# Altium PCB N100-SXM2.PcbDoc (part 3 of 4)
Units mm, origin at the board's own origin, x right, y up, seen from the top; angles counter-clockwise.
Board outline 120 x 145 mm, 4 copper layers (Top Layer, GND, PWR, Bottom Layer), stack 0.603 mm thick; 267 components, 207 nets, 1440 pads, 915 vias.
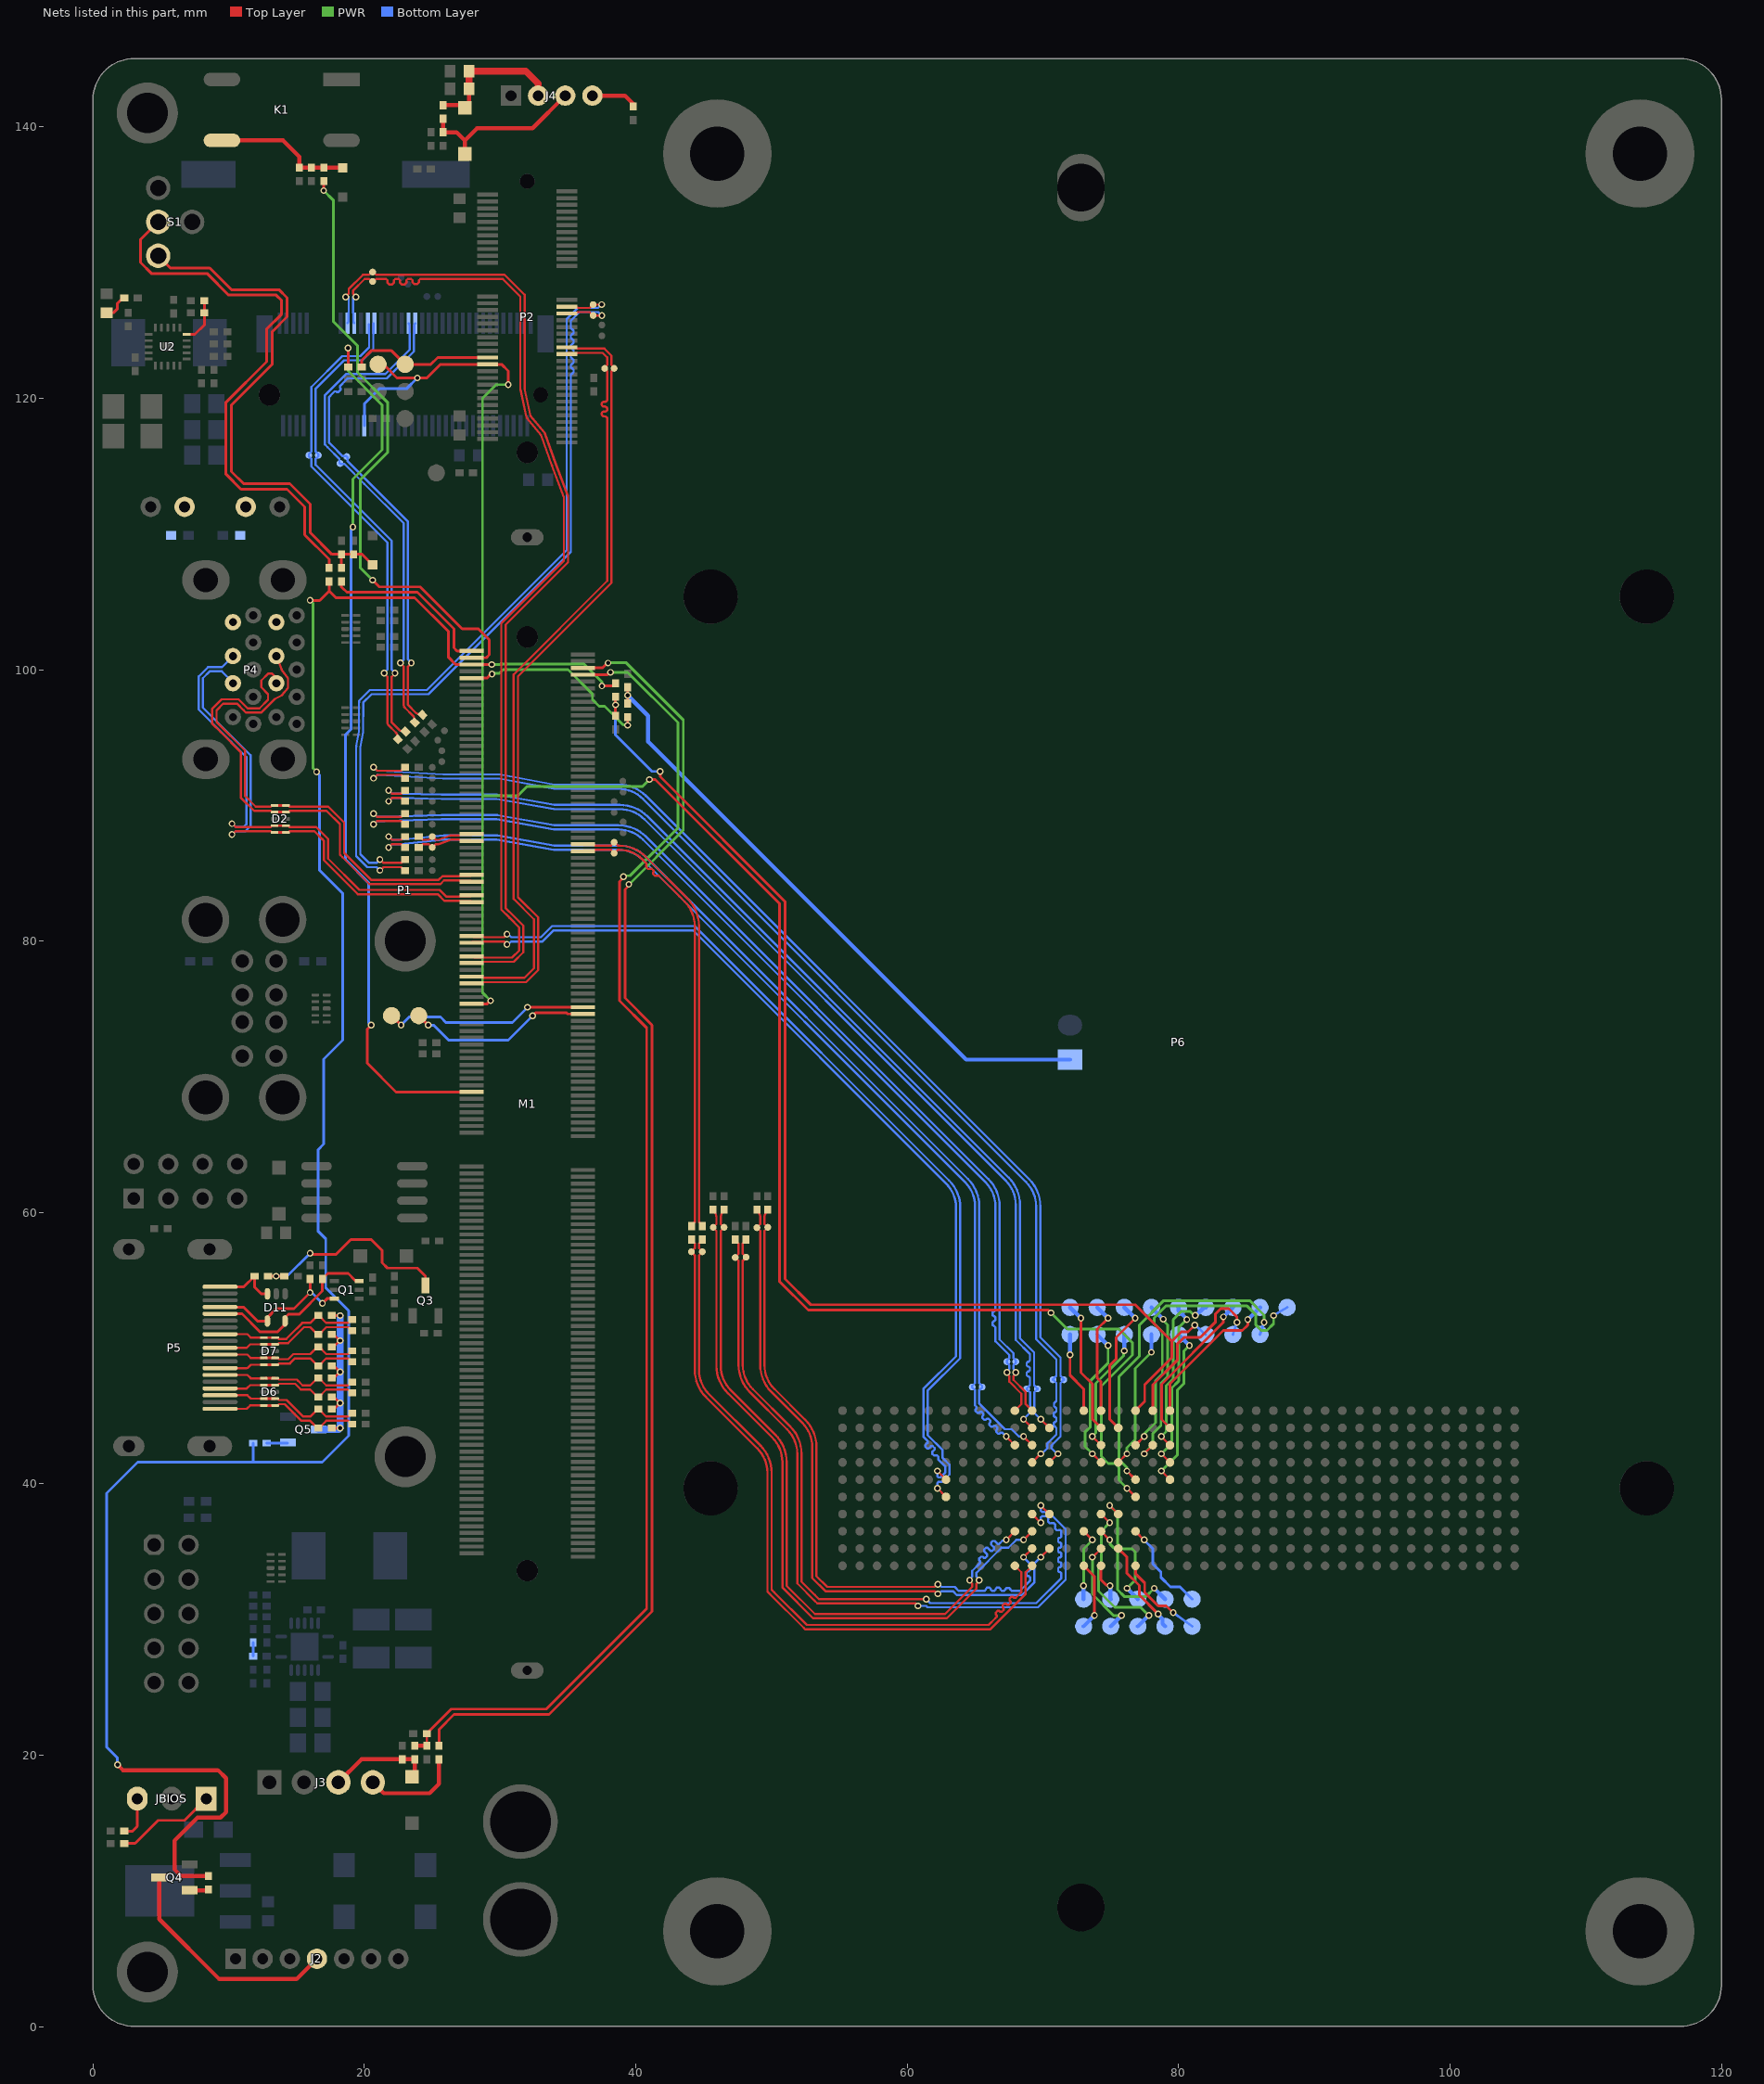
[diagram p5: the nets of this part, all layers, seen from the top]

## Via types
v1: diameter 0.5, hole 0.3, Top Layer to Bottom Layer, tented both sides, 908 vias
v2: diameter 0.6, hole 0.3, Top Layer to Bottom Layer, tented both sides, 6 vias
v3: diameter 1.5, hole 1.5, Top Layer to Bottom Layer, tented both sides, 1 vias

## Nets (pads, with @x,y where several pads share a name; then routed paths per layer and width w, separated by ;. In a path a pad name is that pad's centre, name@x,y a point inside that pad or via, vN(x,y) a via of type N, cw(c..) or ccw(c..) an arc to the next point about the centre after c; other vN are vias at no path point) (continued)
HSIO11_RX_n: C49.2 M1.60 TP32.1 | length 33.8
  Top Layer w0.161: M1.60@36.1,86.625 cw(c36.268,86.457) 36.268,86.694 36.946,86.694 ccw(c36.946,86.737) 36.976,86.707 cw(c37.006,86.677) 37.006,86.719 38.155,86.719 TP32.1@38.4,86.475 38.419,86.475 38.664,86.719 38.8,86.719 cw(c38.8,84.352) 40.474,86.026 40.786,85.714 40.786,85.581 40.772,85.566 40.772,85.438 40.899,85.311 41.027,85.311 41.044,85.328 41.172,85.328 41.299,85.201 41.299,85.073 41.282,85.056 41.282,84.928 41.41,84.8 41.537,84.8 41.552,84.815 41.685,84.815 43.198,83.302 43.601,82.899 cw(c41.804,81.103) 44.344,81.103 44.344,60.054 44.344,59.291 44.1,59.046 C49.2@44.1,59
HSIO11_RX_p: C48.2 M1.58 TP31.1 | length 33.9
  Top Layer w0.161: M1.58@36.1,87.125 ccw(c36.268,87.293) 36.268,87.055 36.946,87.055 cw(c36.946,87.013) 36.976,87.043 ccw(c37.006,87.073) 37.006,87.03 38.156,87.03 TP31.1@38.4,87.275 38.419,87.275 38.664,87.03 38.804,87.03 cw(c38.804,84.362) 40.691,86.249 43.823,83.117 cw(c41.813,81.107) 44.655,81.107 44.655,60.183 44.655,59.29 44.9,59.046 C48.2@44.9,59
HSIO11_TX_n: C41.2 M1.57 TP24.1 | length 4.3
  Top Layer w0.161: C41.2@24,86.9 24.046,86.9 24.291,87.145 24.736,87.145 24.981,86.9 TP24.1@25,86.9 25.019,86.9 25.264,87.144 25.451,87.144 ; 25.452,87.145 ccw(c25.451,87.455) 25.557,87.163 ; 25.557,87.163 26.4,87.469 27.011,87.469 27.036,87.444 27.831,87.444 M1.57@27.9,87.375
HSIO11_TX_p: C40.2 M1.55 TP23.1 | length 4.3
  Top Layer w0.161: C40.2@24,87.7 24.046,87.7 24.291,87.456 24.736,87.456 24.981,87.7 TP23.1@25,87.7 25.019,87.7 25.264,87.455 25.451,87.455 26.293,87.761 cw(c26.4,87.469) 26.399,87.78 ; 26.4,87.78 27.011,87.78 27.036,87.805 27.831,87.805 M1.55@27.9,87.875
JSEL: P6.C19 TP53.1 | length 12.9
  Top Layer w0.161: v1(77.46,42.215) P6.C19@78.095,42.85
  PWR w0.2: v1(77.46,42.215) 77.46,42.242 78.1,42.882 78.1,43.7 78.7,44.3 78.7,47.4 79.2,47.9 79.2,51.719 78.872,52.047 v1(78.872,52.128)
  Bottom Layer w0.3: TP53.1@78,53 v1(78.872,52.128)
JTCK: P6.C20 TP50.1 | length 12.9
  Top Layer w0.161: v1(78.73,43.485) P6.C20@79.365,42.85
  PWR w0.2: v1(78.73,43.485) 79.1,43.855 79.1,47.231 79.6,47.731 79.6,52.1 80.2,52.7 80.858,52.7 81.145,52.413 v1(81.226,52.413)
  Bottom Layer w0.3: v1(81.226,52.413) 81.28,52.413 81.868,53 TP50.1@82,53
JTDI: P6.E20 TP52.1 | length 12.1
  Top Layer w0.161: v1(78.73,40.945) P6.E20@79.365,40.31
  PWR w0.2: v1(78.73,40.945) 79.9,42.115 79.9,46.9 80.4,47.4 80.4,49.8 v1(80.8,50.2)
  Bottom Layer w0.3: TP52.1@80,51 v1(80.8,50.2)
JTDO: P6.D20 TP51.1 | length 12.7
  Top Layer w0.161: v1(78.73,42.215) P6.D20@79.365,41.58
  PWR w0.2: v1(78.73,42.215) 79.5,42.985 79.5,47.066 80,47.566 80,51.5 v1(80.6,52.1)
  Bottom Layer w0.3: TP51.1@80,53 80,52.754 80.6,52.154 v1(80.6,52.1)
JTMS: P6.B20 TP49.1 | length 11.3
  Top Layer w0.2: P6.B20@79.365,44.12 78.745,44.74 78.745,47.345 83.3,51.9 v1(83.3,52.3)
  Bottom Layer w0.3: v1(83.3,52.3) TP49.1@84,53
JTRST: P6.A20 TP48.1 | length 11.2
  Top Layer w0.2: P6.A20@79.365,45.39 79.365,47.365 83.3,51.3 84.7,51.3 85.1,51.7 v1(85.1,52.1)
  Bottom Layer w0.3: v1(85.1,52.1) TP48.1@86,53
M.2_1_RX0_n: C5.1 P1.47 TP73.1 | length 35.9
  Top Layer w0.161: v1(22.255,99.736) 22.255,99.717 22.011,99.472 22.011,96.109 22.529,95.591 ccw(c22.824,95.886) 22.824,95.469 22.951,95.469 cw(c22.951,95.358) C5.1@23.029,95.436
  Bottom Layer w0.161: P1.47@20.681,125.525 20.681,124.761 20.656,124.736 20.656,123.616 19.831,122.791 18.491,122.791 16.405,120.705 16.405,116.064 16.6,115.869 TP73.1@16.6,115.8 16.6,115.731 16.405,115.536 16.405,115.095 22.011,109.489 22.011,100 22.255,99.755 v1(22.255,99.736)
M.2_1_RX0_p: C6.1 P1.49 TP77.1 | length 36.1
  Top Layer w0.161: v1(21.455,99.736) 21.455,99.717 21.7,99.472 21.7,96.108 ccw(c22.009,96.108) 21.79,95.89 22.309,95.371 cw(c22.014,95.076) 22.431,95.076 22.431,94.949 ccw(c22.542,94.949) C6.1@22.464,94.871
  Bottom Layer w0.161: P1.49@20.319,125.456 20.319,124.761 20.345,124.736 20.345,123.744 19.702,123.102 18.362,123.102 16.094,120.834 16.094,116.064 15.9,115.869 TP77.1@15.9,115.8 15.9,115.731 16.094,115.536 16.094,114.966 21.7,109.36 21.7,100 21.455,99.755 v1(21.455,99.736)
M.2_1_RX1_n: C3.1 P1.35 TP67.1 | length 36.8
  Top Layer w0.161: v1(23.455,100.49) 23.455,100.47 23.211,100.226 23.211,97.4 23.783,96.828 ccw(c24.078,97.123) 24.078,96.705 24.205,96.705 cw(c24.205,96.594) C3.1@24.284,96.673
  Bottom Layer w0.161: v1(23.455,100.49) 23.455,100.509 23.211,100.753 23.211,110.909 18.746,115.373 18.746,115.654 TP67.1@18.7,115.7 18.654,115.746 18.373,115.746 17.601,116.519 17.4,116.72 17.4,120.1 17.491,120.191 17.803,120.503 17.936,120.503 17.979,120.461 18.081,120.461 18.234,120.614 18.234,120.716 18.192,120.758 18.192,120.892 18.625,121.325 18.764,121.464 21.654,121.464 23.656,123.466 23.656,124.719 cw(c23.698,124.719) 23.668,124.749 ccw(c23.638,124.779) 23.681,124.779 23.681,125.357 cw(c23.918,125.357) P1.35@23.75,125.525
M.2_1_RX1_p: C4.1 P1.37 TP71.1 | length 36.8
  Top Layer w0.161: v1(22.655,100.49) 22.655,100.47 22.9,100.226 22.9,97.399 ccw(c23.209,97.399) 22.99,97.18 23.563,96.608 cw(c23.268,96.313) 23.685,96.313 23.685,96.186 ccw(c23.796,96.186) C4.1@23.718,96.107
  Bottom Layer w0.161: v1(22.655,100.49) 22.655,100.509 22.9,100.753 22.9,110.78 19.99,113.69 18.527,115.154 18.246,115.154 TP71.1@18.2,115.2 18.153,115.247 18.153,115.527 17.29,116.39 17.089,116.591 17.089,120.229 18.635,121.775 21.525,121.775 23.344,123.595 23.344,124.719 ccw(c23.302,124.719) 23.332,124.749 cw(c23.362,124.779) 23.32,124.779 23.32,125.357 ccw(c23.082,125.357) P1.37@23.25,125.525
M.2_E_n: C63.1 P2.35 TP81.1 | length 58.4
  Top Layer w0.161: v1(21.136,85.2) 21.155,85.2 21.4,85.445 22.71,85.445 22.954,85.2 C63.1@23,85.2 ; P2.35@34.93,126.75 34.999,126.68 35.694,126.68 35.719,126.655 36.592,126.655 36.836,126.9 TP81.1@36.855,126.9 v1(37.481,126.9)
  Bottom Layer w0.161: v1(21.136,85.2) 20.892,85.444 20.216,85.444 19.389,86.271 19.389,94.3 cw(c19.7,94.3) 19.389,94.301 cw(c19.7,94.3) 19.394,94.357 19.591,95.442 ccw(c19.433,95.469) 19.594,95.468 19.594,97.571 19.6,97.578 19.6,97.7 20.4,98.5 24.6,98.5 34.9,108.8 34.9,125.84 35.716,126.655 37.217,126.655 37.461,126.9 v1(37.481,126.9)
M.2_E_p: C64.1 P2.37 TP82.1 | length 58.3
  Top Layer w0.161: v1(21.136,86) 21.155,86 21.4,85.756 22.71,85.756 22.954,86 C64.1@23,86 ; P2.37@34.93,126.25 34.999,126.319 35.694,126.319 35.719,126.344 36.592,126.344 36.836,126.1 TP82.1@36.855,126.1 v1(37.5,126.1)
  Bottom Layer w0.161: v1(21.136,86) 20.892,85.755 20.345,85.755 19.7,86.4 19.7,94.3 19.897,95.386 ccw(c19.591,95.442) 19.899,95.393 ccw(c19.433,95.469) 19.905,95.467 19.911,97.571 20.529,98.189 24.729,98.189 35.211,108.671 35.211,121.292 35.211,121.734 35.305,121.828 35.324,121.828 35.415,121.919 35.415,122.099 35.324,122.189 35.301,122.189 35.211,122.28 35.211,122.46 35.301,122.55 35.324,122.55 35.415,122.641 35.415,122.821 35.324,122.911 35.301,122.911 35.211,123.002 35.211,123.182 35.301,123.272 35.324,123.272 35.415,123.363 35.415,123.543 35.324,123.633 35.301,123.633 35.211,123.724 35.211,123.904 35.301,123.994 35.324,123.994 35.415,124.085 35.415,124.265 35.324,124.355 35.301,124.355 35.211,124.446 35.211,124.626 35.301,124.716 35.324,124.716 35.415,124.807 35.415,124.987 35.324,125.077 35.305,125.077 35.211,125.172 35.211,125.5 35.211,125.711 35.844,126.344 37.236,126.344 37.481,126.1 v1(37.5,126.1)
NetC56_2: C56.2 R37.2 | length 1
  Bottom Layer w0.2: C56.2@11.8,27.3 R37.2@11.8,28.3
NetC67_2: C67.2 D16.1 K1.4 R49.2 R50.2 | length 10
  Top Layer w0.3: K1.4@9.5,139 14,139 15.2,137.8 C67.2@15.2,137 ; C67.2@15.4,137 R50.2@16.1,137 R49.2@17,137 D16.1@18.375,137
NetC68_2: C68.2 D17.1 R46.2 R47.2 S1.2 | length 40.8
  Top Layer w0.2: S1.2@4.8,130.5 5.7,129.6 8.6,129.6 10.2,128 13.7,128 14.3,127.4 14.3,126 13.2,124.9 13.2,122.5 10.2,119.5 10.2,114.6 11.1,113.7 14.5,113.7 16,112.2 16,110.1 17.6,108.5 R46.2@18.3,108.5 ; R47.2@18.3,107.5 R46.2@18.3,108.5 ; D17.1@20.6,107.725 19.825,108.5 C68.2@19.2,108.5 R46.2@18.3,108.5
NetD8_2: D8.2 J3.3 R7.2 R8.1 | length 7.5
  Top Layer w0.3: J3.3@18.08,18 19.78,19.7 R7.2@22.8,19.7 R8.1@23.7,19.7 D8.2@23.7,18.5
NetD9_1: D9.1 J4.2 R18.2 R19.2 R20.1 | length 10.7
  Top Layer w0.3: R20.1@25.8,141.6 D9.1@27.2,141.6 ; D9.1@27.3,141.5 D9.1@27.4,141.4 ; D9.1@27.45,141.45 27.7,141.7 R18.2@27.7,142.8
  Top Layer w0.5: R18.2@27.7,142.8 R19.2@27.7,144.1 31.9,144.1 32.8,143.2 J4.2@32.8,142.3
NetD9_2: D9.2 J4.3 R20.2 R21.1 | length 12.6
  Top Layer w0.3: R20.2@25.8,140.6 R21.1@25.8,139.6 26.8,139.6 27.4,139 ; D9.2@27.4,138 27.4,139 ; J4.3@34.8,142.3 32.4,139.9 28.3,139.9 27.4,139
NetD14_2: D14.2 R44.2 | length 2
  Top Layer w0.2: D14.2@1,126.3 1.5,126.3 1.8,126.6 1.8,127 2.2,127.4 R44.2@2.3,127.4
NetJ3_4: J3.4 R9.1 | length 7.3
  Top Layer w0.3: J3.4@20.62,18 21.22,17.4 21.42,17.2 24.8,17.2 25.5,17.9 R9.1@25.5,19.7
NetJ4_4: J4.4 R22.1 | length 3.2
  Top Layer w0.3: J4.4@36.8,142.3 39.2,142.3 R22.1@39.8,141.7
NetJBIOS_1: JBIOS.1 R2.1 | length 7.4
  Top Layer w0.2: R2.1@2.3,13.5 3.1,13.5 4.8,15.2 6.74,15.2 JBIOS.1@8.34,16.8
NetJBIOS_3: JBIOS.3 R3.1 | length 3.1
  Top Layer w0.2: R3.1@2.3,14.4 2.9,14.4 3.26,14.76 JBIOS.3@3.26,16.8
NetQ3_3: Q3.3 R29.2 R31.2 | length 15.7
  Top Layer w0.2: R29.2@12.9,55.3 v1(13.5,55.3) R31.2@14.1,55.3 ; v1(16,57) 16.1,56.9 17.9,56.9 19,58 20.5,58 21.3,57.2 21.3,56.3 21.7,55.9 23.9,55.9 24.5,55.3 Q3.3@24.5,54.625
  Bottom Layer w0.2: v1(13.5,55.3) 14.3,55.3 v1(16,57)
NetQ4_1: Q4.1 R30.1 | length 1.3
  Top Layer w0.3: Q4.1@7.125,10.05 R30.1@8.45,10.05
NetQ5_1: Q5.1 R23.1 | length 1.5
  Bottom Layer w0.2: R23.1@12.8,43 Q5.1@14.325,43
NetQ5_3: Q5.3 R14.1 R15.2 R51.1 R52.2 R53.1 R54.2 R55.1 R56.2 | length 15.4
  Top Layer w0.2: R15.2@17.6,44.1 v1(18.2,44.1) ; R52.2@17.6,45.5 17.75,45.5 v1(18.2,45.95) R54.2@17.75,46.4 ; R56.2@17.6,47.8 17.75,47.8 v1(18.2,48.25) R14.1@17.75,48.7 ; R51.1@17.6,50.1 17.75,50.1 v1(18.2,50.55) R53.1@17.75,51 ; R55.1@17.6,52.4 v1(18.2,52.4)
  Bottom Layer w0.5: Q5.3@16.625,44 18.1,44 v1(18.2,44.1) v1(18.2,45.95) v1(18.2,48.25) v1(18.2,52.4)
NetR12_1: R12.1 R40.1 U2.15 | length 3.4
  Top Layer w0.2: U2.15@6.9,124.7 7.5,124.7 8.2,125.4 R40.1@8.2,127.2
NetR48_2: R48.2 S1.4 | length 41.6
  Top Layer w0.2: S1.4@4.8,133 3.5,131.7 3.5,130 4.3,129.2 8.4,129.2 10,127.6 13.5,127.6 13.9,127.2 13.9,126.2 12.8,125.1 12.8,122.7 9.8,119.7 9.8,114.4 10.9,113.3 14.3,113.3 15.6,112 15.6,109.934 17.4,108.134 R48.2@17.4,107.5
NTC: NTC.1 R16.2 R17.1 | length 46
  Top Layer w0.2: R17.1@39.4,97.5 v1(39.4,98.1) R16.2@39.4,98.7
  Bottom Layer w0.3: v1(39.4,98.1) 40.9,96.6 40.9,94.7 64.34,71.26 NTC.1@72,71.26
PERST#: M1.105 P1.50 P2.52 P6.F18 TP61.1 | length 161.9
  Top Layer w0.161: v1(76.19,39.675) P6.F18@76.825,39.04
  Top Layer w0.2: TP61.1@21,122.5 21.205,122.295 21.605,122.295 22.4,121.5 24.6,121.5 25.6,122.5 P2.52@29.07,122.5 30.1,122.5 30.6,122 v1(30.6,121) ; M1.105@27.9,75.375 29.044,75.375 29.269,75.6 v1(29.3,75.6) ; v1(41,91.9) 41.434,91.9 50.6,82.734 50.6,54.9 52.7,52.8 70.4,52.8 v1(70.6,52.6)
  PWR w0.2: v1(29.3,75.6) 28.7,76.2 28.7,90.7 ; v1(30.6,121) 29.7,121 28.7,120 28.7,90.7 ; v1(41,91.9) 40.5,91.4 32,91.4 31.3,90.7 28.7,90.7 ; v1(70.6,52.6) 71.8,51.4 75.6,51.4 76.6,50.4 76.6,49.5 74.3,47.2 74.3,42.029 74.829,41.5 75.3,41.5 75.6,41.2 75.6,40.265 v1(76.19,39.675)
  Bottom Layer w0.2: P1.50@20,117.975 20,119.6 21.1,120.7 23.1,120.7 v1(23.9,121.5)
PSON#: J2.4 Q4.3 | length 17.2
  Top Layer w0.3: Q4.3@4.875,11 4.875,7.925 9.3,3.5 15,3.5 J2.4@16.5,5
PWRBTN: M1.1 R47.1 | length 12.9
  Top Layer w0.2: R47.1@18.3,106.5 18.3,106.1 18.5,105.9 ; 18.4,106 18.7,105.7 23.9,105.7 26.6,103 26.6,101.6 26.825,101.375 M1.1@27.9,101.375
REFCLK0_n: M1.87 P6.E7 | length 69.4
  Top Layer w0.161: M1.87@27.9,79.875 cw(c28.068,79.707) 28.068,79.944 28.746,79.944 ccw(c28.746,79.987) 28.776,79.957 cw(c28.806,79.927) 28.806,79.969 30.281,79.969 v1(30.5,79.75) ; v1(62.22,40.945) P6.E7@62.855,40.31
  Bottom Layer w0.161: v1(30.5,79.75) 30.594,79.75 30.814,79.969 33.131,79.969 33.951,80.789 44.211,80.789 62.856,62.144 cw(c61.06,60.348) 63.6,60.348 63.6,49.4 61.189,46.989 61.189,43.471 61.501,43.159 61.501,43.026 61.332,42.857 61.332,42.729 61.46,42.601 61.587,42.601 61.759,42.773 61.887,42.773 62.015,42.646 62.015,42.518 61.843,42.346 61.843,42.218 61.97,42.091 62.203,42.091 62.297,41.996 62.297,41.786 62.321,41.763 62.378,41.706 62.8,41.283 62.8,40.818 62.448,40.466 62.314,40.466 62.22,40.56 v1(62.22,40.945)
REFCLK0_p: M1.85 P6.F7 | length 69.5
  Top Layer w0.161: M1.85@27.9,80.375 ccw(c28.068,80.543) 28.068,80.305 28.746,80.305 cw(c28.746,80.263) 28.776,80.293 ccw(c28.807,80.323) 28.807,80.28 30.281,80.28 v1(30.5,80.5) ; v1(62.22,39.675) P6.F7@62.855,39.04
  Bottom Layer w0.161: v1(30.5,80.5) 30.594,80.5 30.814,80.28 33.002,80.28 33.822,81.1 44.34,81.1 63.079,62.361 cw(c61.069,60.352) 63.911,60.352 63.911,49.271 61.5,46.86 61.5,43.6 62.608,42.492 62.608,41.915 63.111,41.412 63.111,40.689 62.577,40.155 62.314,40.155 62.22,40.06 v1(62.22,39.675)
REFCLK1_n: M1.93 P1.55 TP79.1 | length 72.6
  Top Layer w0.161: v1(18.625,127.453) 18.625,127.497 18.845,127.717 18.845,128.057 19.893,129.105 20.336,129.105 20.531,129.3 TP79.1@20.6,129.3 20.669,129.3 20.864,129.105 30.323,129.105 31.8,127.629 31.8,120.7 32.239,118.699 33.229,117.514 cw(c32.866,117.213) 33.308,117.378 cw(c33.017,117.268) 33.31,117.373 34.108,115.154 34.991,112.811 cw(c34.7,112.7) 35.011,112.7 35.011,107.911 30.4,103.3 30.4,82.44 31.02,81.82 31.711,81.129 31.711,79.171 31.009,78.469 28.806,78.469 ccw(c28.806,78.427) 28.776,78.457 cw(c28.746,78.487) 28.746,78.444 28.068,78.444 ccw(c28.068,78.207) M1.93@27.9,78.375
  Bottom Layer w0.161: P1.55@18.75,125.525 ccw(c18.582,125.693) 18.82,125.693 18.82,126.271 cw(c18.862,126.271) 18.832,126.301 ccw(c18.802,126.331) 18.845,126.331 v1@18.845,127.453
REFCLK1_p: M1.91 P1.53 TP78.1 | length 72.6
  Top Layer w0.161: v1(19.375,127.453) 19.375,127.497 19.156,127.717 19.156,127.929 20.021,128.794 20.336,128.794 20.531,128.6 TP78.1@20.6,128.6 20.669,128.6 20.864,128.794 21.048,128.794 21.589,128.794 21.705,128.679 21.705,128.508 21.82,128.393 22.05,128.393 22.166,128.508 22.166,128.679 22.281,128.794 22.511,128.794 22.627,128.679 22.627,128.508 22.742,128.393 22.972,128.393 23.088,128.508 23.088,128.679 23.203,128.794 23.433,128.794 23.549,128.679 23.549,128.535 23.664,128.42 23.894,128.42 24.01,128.535 24.01,128.679 24.125,128.794 25.967,128.794 30.195,128.794 31.489,127.5 31.489,120.7 ccw(c31.8,120.7) 31.496,120.632 31.935,118.633 ccw(c32.239,118.699) 32,118.5 32.989,117.316 cw(c32.866,117.213) 33.017,117.268 33.815,115.049 ccw(c33.961,115.101) 33.816,115.047 ccw(c34.108,115.154) 33.818,115.041 34.7,112.7 34.7,108.04 30.089,103.429 30.089,82.311 30.692,81.708 31.4,81 31.4,79.3 30.88,78.78 28.807,78.78 cw(c28.807,78.823) 28.776,78.793 ccw(c28.746,78.763) 28.746,78.805 28.068,78.805 cw(c28.068,79.043) M1.91@27.9,78.875
  Bottom Layer w0.161: v1@19.156,127.453 19.156,126.331 ccw(c19.198,126.331) 19.168,126.301 cw(c19.138,126.271) 19.181,126.271 19.181,125.693 ccw(c19.418,125.693) P1.53@19.25,125.525
REFCLK2_n: M1.99 P2.47 TP86.1 | length 57.8
  Top Layer w0.161: M1.99@27.9,76.875 27.97,76.944 28.764,76.944 28.789,76.969 31.909,76.969 32.811,77.871 32.811,81.729 31.458,83.082 31.311,83.229 31.311,99.511 38.211,106.411 38.211,122.011 TP86.1@38.4,122.2 38.4,122.269 38.205,122.464 38.205,123.134 37.684,123.655 35.719,123.655 35.694,123.68 34.999,123.68 P2.47@34.93,123.75
REFCLK2_p: M1.97 P2.49 TP87.1 | length 57.8
  Top Layer w0.161: M1.97@27.9,77.375 27.97,77.305 28.764,77.305 28.789,77.28 31.78,77.28 32.5,78 32.5,81.6 31,83.1 31,99.64 37.9,106.54 37.9,118.4 37.9,118.481 ccw(c37.72,118.481) 37.72,118.661 37.67,118.661 cw(c37.67,118.842) 37.67,119.022 37.72,119.022 ccw(c37.72,119.203) 37.72,119.383 37.67,119.383 cw(c37.67,119.564) 37.67,119.744 37.72,119.744 ccw(c37.72,119.925) 37.9,119.925 37.9,120.9 37.9,122 TP87.1@37.7,122.2 37.7,122.269 37.894,122.464 37.894,123.006 37.556,123.344 35.719,123.344 35.694,123.319 34.999,123.319 P2.49@34.93,123.25
RSTBTN: M1.3 R49.1 | length 45.5
  Top Layer w0.2: v1(17,135.3) R49.1@17,136 ; v1(20.6,106.6) 21.1,106.1 24.1,106.1 27.2,103 28.4,103 29.2,102.2 29.2,101.1 28.975,100.875 M1.3@27.9,100.875
  PWR w0.2: v1(17,135.3) 17.7,134.6 17.7,125.675 19.5,123.875 19.5,121.9 21.7,119.7 21.7,116 19.7,114 19.7,107.5 v1(20.6,106.6)
RSVD_A15: P6.A15 TP40.1 | length 6
  Top Layer w0.2: v1(72,49.5) 72,48 73.015,46.985 P6.A15@73.015,45.39
  Bottom Layer w0.3: v1(72,49.5) TP40.1@72,51
RSVD_A16: P6.A16 TP39.1 | length 8.4
  Top Layer w0.2: P6.A16@74.285,45.39 74.285,47.515 74,47.8 74,51.4 v1(74.8,52.2)
  Bottom Layer w0.3: TP39.1@74,53 v1(74.8,52.2)
RSVD_B16: P6.B16 TP38.1 | length 9.8
  Top Layer w0.2: v1(72.8,52.2) 72.8,48.2 73.65,47.35 73.65,44.755 P6.B16@74.285,44.12
  Bottom Layer w0.3: TP38.1@72,53 v1(72.8,52.2)
RSVD_B17: P6.B17 TP37.1 | length 10.3
  Top Layer w0.2: P6.B17@75.555,44.12 74.92,44.755 74.92,48.72 75.4,49.2 75.4,50.8 v1(76.8,52.2)
  Bottom Layer w0.3: TP37.1@76,53 v1(76.8,52.2)
RSVD_C16: P6.C16 TP47.1 | length 9.4
  Top Layer w0.161: v1(73.65,43.485) P6.C16@74.285,42.85
  PWR w0.2: v1(73.65,43.485) 73.65,43.502 73.9,43.752 73.9,47.4 75.961,49.461 75.961,49.761 v1(76,49.8)
  Bottom Layer w0.3: v1(76,49.8) TP47.1@76,51
RSVD_D16: P6.D16 TP46.1 | length 10.9
  Top Layer w0.161: v1(73.65,42.215) P6.D16@74.285,41.58
  PWR w0.2: v1(73.65,42.215) 73.1,42.765 73.1,43.8 73.5,44.2 73.5,47.6 74.8,48.9 v1(74.8,50.2)
  Bottom Layer w0.3: TP46.1@74,51 v1(74.8,50.2)
RSVD_D17: P6.D17 TP45.1 | length 10.4
  Top Layer w0.161: P6.D17@75.555,41.58 v1(76.19,42.215)
  PWR w0.2: v1(76.19,42.215) 76.19,42.648 76.8,43.258 76.8,48.5 v1(78,49.7)
  Bottom Layer w0.3: v1(78,49.7) TP45.1@78,51
RSVD_G16: P6.G16 TP36.1 | length 11.8
  Top Layer w0.161: P6.G16@74.285,37.77 v1(74.92,37.135)
  PWR w0.2: v1(74.92,37.135) 74.3,36.515 74.3,34.2 74.1,34 74.1,32.1 75.3,30.9 77.2,30.9 v1(77.8,30.3)
  Bottom Layer w0.3: TP36.1@77,29.5 v1(77.8,30.3)
RSVD_G17: P6.G17 TP35.1 | length 9.6
  Top Layer w0.161: v1(74.92,38.405) P6.G17@75.555,37.77
  PWR w0.2: v1(74.92,38.405) 75.5,37.825 75.5,35.6 75.9,35.2 76.6,35.2 76.8,35 76.8,32.9 v1(76.2,32.3)
  Bottom Layer w0.3: v1(76.2,32.3) TP35.1@77,31.5
RSVD_H15: P6.H15 TP34.1 | length 5.5
  Top Layer w0.161: P6.H15@73.015,36.5 v1(73.65,35.865)
  PWR w0.2: v1(73,32.5) 73,35.215 v1(73.65,35.865)
  Bottom Layer w0.3: TP34.1@73,31.5 v1(73,32.5)
RSVD_H16: P6.H16 TP33.1 | length 9.1
  Top Layer w0.161: P6.H16@74.285,36.5 v1(74.92,35.865)
  PWR w0.2: v1(74.92,35.865) 74.966,35.819 74.966,35.534 75.5,35 75.5,32.2 76,31.7 77.6,31.7 v1(78.2,32.3)
  Bottom Layer w0.3: v1(78.2,32.3) TP33.1@79,31.5
RSVD_J16: P6.J16 TP44.1 | length 7.6
  Top Layer w0.161: v1(73.65,34.595) P6.J16@74.285,35.23
  PWR w0.2: v1(73.65,34.595) 73.65,31.85 75.2,30.3 v1(75.8,30.3)
  Bottom Layer w0.3: TP44.1@75,29.5 v1(75.8,30.3)
RSVD_J17: P6.J17 TP43.1 | length 7.2
  Top Layer w0.2: P6.J17@75.555,35.23 76.2,34.585 76.2,33.4 77.1,32.5 77.1,31.8 v1(78.5,30.4)
  Bottom Layer w0.3: v1(78.5,30.4) 78.5,30.346 78.814,30.031 78.814,29.686 TP43.1@79,29.5
RSVD_K15: P6.K15 TP42.1 | length 5.1
  Top Layer w0.2: P6.K15@73.015,33.96 73.8,33.175 v1(73.8,30.3)
  Bottom Layer w0.3: TP42.1@73,29.5 v1(73.8,30.3)
RSVD_K16: P6.K16 TP41.1 | length 2.9
  Top Layer w0.2: P6.K16@74.285,33.96 74.285,32.915 74.661,32.539 74.911,32.539 v1(74.95,32.5)
  Bottom Layer w0.3: v1(74.95,32.5) 74.975,32.475 74.975,31.525 TP41.1@75,31.5
SLS_S0: M1.5 R23.2 R30.2 R32.1 R48.1 | length 153.7
  Top Layer w0.2: v1(16,105.1) 16.7,105.1 17.4,105.8 ; R48.1@17.4,106.5 17.4,105.8 ; v1(29.375,100.375) M1.5@27.9,100.375 26.725,100.375 26.2,100.9 26.2,102.8 23.7,105.3 17.9,105.3 17.4,105.8 ; v1(37.5,98.8) 38.3,98.8 R32.1@38.5,99
  Top Layer w0.3: v1(1.8,19.3) 2.2,18.9 9.2,18.9 9.8,18.3 9.8,15.8 9.4,15.4 7.7,15.4 6,13.7 6,11.6 6.5,11.1 R30.2@8.5,11.1
  PWR w0.2: v1(16,105.1) 16.2,104.9 16.2,92.754 v1(16.478,92.476) ; v1(29.375,100.375) 30.009,100.375 30.034,100.4 36.2,100.4 37.5,99.1 v1(37.5,98.8)
  Bottom Layer w0.2: v1(1.8,19.3) 1.8,19.8 1,20.6 1,39.3 3.3,41.6 11.8,41.6 ; R23.2@11.8,43 11.8,41.6 ; v1(16.478,92.476) 16.478,92.431 16.7,92.209 16.7,85.213 18.4,83.513 18.4,72.7 17,71.3 17,65.033 16.6,64.633 16.6,58.6 17.15,58.05 17.15,54.45 18.85,52.75 18.85,43.55 16.9,41.6 11.8,41.6
SMB_CLK: M1.106 TP89.1 | length 15.3
  Top Layer w0.2: TP89.1@22,74.5 v1(22.7,73.8) ; v1(32.025,75.125) M1.106@36.1,75.125
  Bottom Layer w0.2: v1(22.7,73.8) 23.3,74.4 25.6,74.4 26,74 30.9,74 v1(32.025,75.125)
SMB_DATA: M1.108 TP88.1 | length 13.7
  Top Layer w0.2: TP88.1@24,74.5 v1(24.7,73.8) ; v1(32.4,74.5) 32.6,74.7 34.9,74.7 34.975,74.625 M1.108@36.1,74.625
  Bottom Layer w0.2: v1(24.7,73.8) 25.1,73.8 26.2,72.7 30.6,72.7 v1(32.4,74.5)
SUSCLK: M1.131 R41.1 | length 65.7
  Top Layer w0.2: R41.1@18.8,122.3 v1(18.8,123.7) ; v1(20.5,73.8) 20.2,73.5 20.2,71 22.325,68.875 M1.131@27.9,68.875
  PWR w0.2: v1(18.8,123.7) 18.8,122 21.3,119.5 21.3,116.2 19.15,114.05 v1(19.15,110.5)
  Bottom Layer w0.2: v1(19.15,110.5) 19.15,110.419 19,110.269 19,95.6 18.6,95.2 18.6,86 20.3,84.3 20.3,74 v1(20.5,73.8)
SUSCLK_E: P2.50 R41.2 TP60.1 | length 10.7
  Top Layer w0.2: R41.2@19.8,122.3 19.8,122.8 20.5,123.5 22,123.5 TP60.1@23,122.5 24.9,122.5 25.4,123 P2.50@29.07,123
SXM_ADDR0: P6.H18 TP55.1 | length 7.1
  Top Layer w0.2: P6.H18@76.825,36.5 v1(77.46,35.865)
  Bottom Layer w0.2: v1(77.46,35.865) 78.1,35.225 78.1,34.1 78.7,33.5 78.7,33.1 79.4,32.4 80.1,32.4 TP55.1@81,31.5
SXM_ADDR1: P6.C18 TP54.1 | length 22.8
  Top Layer w0.2: P6.C18@76.825,42.85 v1(77.46,43.485)
  PWR w0.2: v1(77.46,43.485) 77.46,43.66 78.3,44.5 78.3,47.6 78.8,48.1 78.8,51.2 78.2,51.8 78.2,52.234 79.066,53.1 85.05,53.1 85.7,52.45 85.7,51.7 86.1,51.3 86.5,51.3 87,51.8 v1(87,52.4)
  Bottom Layer w0.2: v1(87,52.4) TP54.1@88,53
SXM_PERX0_n: C35.1 P6.D12 TP4.1 | length 85.6
  Top Layer w0.161: v1(20.679,92) 20.699,92 20.943,92.244 22.709,92.245 22.954,92 C35.1@23,92 ; P6.D12@69.205,41.58 v1(69.84,42.215)
  Bottom Layer w0.161: v1(20.679,92) 20.699,92 20.943,92.244 21.001,92.241 cw(c20.993,92.08) 21.003,92.241 25.801,91.97 ccw(c25.82,92.28) 25.82,91.969 ; 25.822,91.969 29.93,91.969 33.943,91.225 ; 34,91.219 38.728,91.219 cw(c38.728,88.679) 40.525,90.476 68.756,62.244 cw(c66.96,60.448) 69.5,60.448 69.5,50.66 70.989,49.171 70.989,47.955 70.744,47.71 TP4.1@70.744,47.672 70.989,47.427 70.989,47.005 70.989,46.099 70.895,46.005 70.89,46.005 70.817,45.933 70.817,45.716 70.89,45.644 70.917,45.644 70.989,45.572 70.989,45.355 70.917,45.283 70.877,45.283 70.805,45.211 70.805,44.994 70.877,44.922 70.917,44.922 70.989,44.85 70.989,44.633 70.917,44.561 70.877,44.561 70.805,44.489 70.805,44.272 70.877,44.2 70.895,44.2 70.989,44.106 70.989,44.025 70.989,43.625 70.32,42.956 70.32,42.625 69.91,42.215 v1(69.84,42.215)
SXM_PERX0_p: C34.1 P6.D13 TP2.1 | length 85.6
  Top Layer w0.161: v1(20.679,92.8) 20.699,92.8 20.943,92.555 22.709,92.556 22.954,92.8 C34.1@23,92.8 ; P6.D13@70.475,41.58 v1(71.11,42.215)
  Bottom Layer w0.161: v1(20.679,92.8) 20.699,92.8 20.943,92.555 cw(c20.943,92.4) 20.945,92.555 cw(c20.943,92.244) 20.962,92.555 21.019,92.552 ; 21.021,92.552 25.82,92.28 29.929,92.28 cw(c29.93,91.969) 29.988,92.275 34,91.53 38.732,91.53 cw(c38.732,88.688) 40.742,90.698 68.979,62.461 cw(c66.969,60.452) 69.811,60.452 69.811,50.789 71.3,49.3 71.3,47.955 71.545,47.71 TP2.1@71.545,47.672 71.3,47.427 71.3,43.496 70.631,42.827 70.631,42.625 71.04,42.215 v1(71.11,42.215)
SXM_PERX1_n: C37.1 P6.B12 TP8.1 | length 78.3
  Top Layer w0.161: v1(21.779,90.3) 21.799,90.3 22.043,90.544 22.709,90.545 22.954,90.3 C37.1@23,90.3 ; v1(68.57,44.755) P6.B12@69.205,44.12
  Bottom Layer w0.161: v1(21.779,90.3) 21.799,90.3 22.043,90.544 22.6,90.544 25.692,90.47 ; 25.7,90.469 29.747,90.469 33.945,89.724 ; 34,89.719 38.828,89.719 cw(c38.828,87.179) 40.625,88.976 67.256,62.344 cw(c65.46,60.548) 68,60.548 68,50.6 69.044,49.556 69.044,49.535 69.044,49.094 68.95,48.999 68.892,48.999 68.801,48.909 68.801,48.728 68.892,48.638 68.954,48.638 69.044,48.548 69.044,48.367 68.954,48.277 68.892,48.277 68.801,48.187 68.801,48.006 68.892,47.916 68.95,47.916 69.044,47.822 69.044,47.264 68.8,47.019 68.8,46.986 69.05,46.736 69.05,46.027 69.05,45.235 v1(68.57,44.755)
SXM_PERX1_p: C36.1 P6.B13 TP6.1 | length 78.3
  Top Layer w0.161: v1(21.779,91.1) 21.799,91.1 22.043,90.855 22.709,90.856 22.954,91.1 C36.1@23,91.1 ; v1(69.84,44.755) P6.B13@70.475,44.12
  Bottom Layer w0.161: v1(21.779,91.1) 21.799,91.1 22.043,90.855 22.6,90.855 cw(c22.6,90.544) 22.609,90.855 25.7,90.78 29.744,90.78 ccw(c29.745,90.941) 29.745,90.78 cw(c29.747,90.469) 29.803,90.775 34,90.03 38.832,90.03 cw(c38.832,87.188) 40.842,89.198 67.479,62.561 cw(c65.469,60.552) 68.311,60.552 68.311,50.729 69.356,49.684 69.356,47.264 69.6,47.019 69.6,46.975 69.361,46.736 69.361,46.156 69.361,45.234 v1(69.84,44.755)
SXM_PERX2_n: C39.1 P6.A11 TP13.1 | length 77.2
  Top Layer w0.161: v1(20.679,88.6) 20.699,88.6 20.943,88.844 22.709,88.845 22.954,88.6 C39.1@23,88.6 ; v1(67.346,48.2) 67.346,48.108 67.518,47.937 67.518,47.537 68.415,46.64 68.415,45.87 P6.A11@67.935,45.39
  Bottom Layer w0.161: v1(20.679,88.6) 20.699,88.6 20.943,88.844 21.5,88.844 ccw(c21.5,89.155) 21.501,88.844 ccw(c21.5,89.155) 21.51,88.845 25.7,88.969 29.747,88.969 33.945,88.224 ccw(c34,88.53) 33.998,88.219 ; 34,88.219 38.728,88.219 cw(c38.728,85.679) 40.524,87.476 65.756,62.244 cw(c63.96,60.448) 66.5,60.448 66.5,53.25 66.5,52.808 66.406,52.714 66.377,52.714 66.304,52.642 66.304,52.425 66.377,52.353 66.428,52.353 66.5,52.281 66.5,52.064 66.428,51.992 66.377,51.992 66.304,51.92 66.304,51.703 66.377,51.631 66.406,51.631 66.5,51.537 66.5,50.75 66.5,50.499 ; 66.506,50.505 67.518,49.494 67.518,49.263 67.346,49.092 TP13.1@67.346,49 67.346,48.908 67.518,48.737 67.518,48.463 67.346,48.292 v1(67.346,48.2) v1@67.3,48.246
SXM_PERX2_p: C38.1 P6.A12 TP10.1 | length 77.3
  Top Layer w0.161: v1(20.679,89.4) 20.699,89.4 20.943,89.155 22.709,89.156 22.954,89.4 C38.1@23,89.4 ; v1(68,48.2) 68,48.108 67.829,47.937 67.829,47.665 68.726,46.768 68.726,45.87 P6.A12@69.205,45.39
  Bottom Layer w0.161: v1(20.679,89.4) 20.699,89.4 20.943,89.155 21.5,89.155 25.689,89.28 cw(c25.7,88.969) 25.697,89.28 cw(c25.699,89.125) 25.698,89.28 29.744,89.28 ccw(c29.745,89.441) 29.745,89.28 cw(c29.747,88.969) 29.803,89.275 34,88.53 38.732,88.53 cw(c38.732,85.688) 40.742,87.698 65.979,62.461 cw(c63.969,60.452) 66.811,60.452 66.811,50.64 67.829,49.622 67.829,49.263 68,49.092 TP10.1@68,49 68,48.908 67.829,48.737 67.829,48.463 68,48.292 v1(68,48.2) v1@67.991,48.209
SXM_PERX3_n: C41.1 P6.C11 TP18.1 | length 76.5
  Top Layer w0.161: v1@21.799,86.9 22.043,87.144 22.709,87.145 22.954,86.9 C41.1@23,86.9 ; v1(67.3,43.485) P6.C11@67.935,42.85
  Bottom Layer w0.161: v1(21.779,86.9) 21.799,86.9 22.043,87.144 22.6,87.144 ccw(c22.6,87.455) 22.601,87.144 ; 22.602,87.144 ccw(c22.6,87.455) 22.631,87.146 25.9,87.469 29.747,87.469 33.945,86.724 ccw(c34,87.03) 33.998,86.719 ; 33.999,86.719 ccw(c34,87.03) 34,86.719 38.728,86.719 cw(c38.728,84.179) 40.524,85.976 64.256,62.244 cw(c62.46,60.448) 65,60.448 65,47.428 64.792,47.22 TP18.1@64.792,47.136 64.792,47.108 65,46.9 65,45.934 65,45.785 65.098,45.687 65.098,45.554 65.035,45.491 65.035,45.363 65.162,45.235 65.29,45.235 65.356,45.301 65.484,45.301 65.611,45.174 65.611,45.046 65.539,44.974 65.539,44.846 65.667,44.719 65.794,44.719 65.867,44.791 65.994,44.791 66.122,44.663 66.122,44.536 66.05,44.463 66.05,44.336 66.177,44.208 66.305,44.208 66.377,44.28 66.505,44.28 66.632,44.153 66.632,44.025 66.56,43.953 66.56,43.825 66.688,43.698 66.816,43.698 66.885,43.767 67.018,43.767 67.075,43.71 v1(67.3,43.485)
SXM_PERX3_p: C40.1 P6.C12 TP16.1 | length 76.5
  Top Layer w0.161: v1(21.779,87.7) 21.799,87.7 22.043,87.455 22.709,87.456 22.954,87.7 C40.1@23,87.7 ; v1(68.57,43.485) P6.C12@69.205,42.85
  Bottom Layer w0.161: v1(21.779,87.7) 21.799,87.7 22.043,87.455 22.6,87.455 25.868,87.779 cw(c25.9,87.469) 25.898,87.78 ; 25.898,87.78 cw(c25.9,87.625) 25.9,87.78 29.745,87.78 ccw(c29.746,87.941) 29.746,87.78 cw(c29.747,87.469) 29.803,87.775 34,87.03 38.732,87.03 cw(c38.732,84.188) 40.742,86.198 64.479,62.461 cw(c62.469,60.452) 65.311,60.452 65.311,60.319 65.311,47.428 65.519,47.22 TP16.1@65.519,47.136 65.519,47.108 65.311,46.9 65.311,45.914 67.2,44.025 67.7,44.025 68.24,43.485 v1(68.57,43.485)
SXM_PETX0_n: C43.1 P6.J13 TP1.1 | length 49.2
  Top Layer w0.161: v1(62.264,31.895) 62.194,31.895 62,32.089 53.971,32.089 53,33.06 53,42.708 ccw(c50.46,42.708) 52.256,44.504 50.004,46.756 cw(c52.018,48.77) 49.17,48.77 49.17,58.636 TP1.1@48.925,58.881 48.925,58.9 49.17,59.144 49.17,59.61 ccw(c48.446,59.61) C43.1@48.958,60.121 ; v1(69.84,34.595) P6.J13@70.475,35.23 ; C43.1@48.958,60.121 cw(c49.036,60.2) C43.1@48.925,60.2 ccw(c49.036,60.2) C43.1@48.958,60.121
  Bottom Layer w0.161: v1(62.264,31.895) 62.333,31.895 62.528,32.089 63.371,32.089 63.66,31.8 68.44,31.8 69.361,32.721 69.361,34.116 v1(69.84,34.595)
SXM_PETX0_p: C42.1 P6.J12 TP3.1 | length 49.2
  Top Layer w0.161: v1(62.264,32.595) 62.195,32.595 62,32.4 54.1,32.4 53.311,33.189 53.311,42.712 ccw(c50.469,42.712) 52.479,44.721 50.224,46.976 cw(c52.021,48.772) 49.481,48.772 49.481,58.636 49.725,58.881 TP3.1@49.725,58.9 49.481,59.144 49.481,59.61 cw(c50.204,59.61) C42.1@49.693,60.121 ; v1(68.57,34.595) P6.J12@69.205,35.23 ; C42.1@49.693,60.121 ccw(c49.614,60.2) C42.1@49.725,60.2 cw(c49.614,60.2) C42.1@49.693,60.121
  Bottom Layer w0.161: v1(62.264,32.595) 62.333,32.595 62.528,32.4 63.5,32.4 63.789,32.111 65.622,32.111 65.703,32.111 65.797,32.205 65.797,32.252 65.887,32.342 66.068,32.342 66.158,32.252 66.158,32.201 66.248,32.111 66.429,32.111 66.519,32.201 66.519,32.252 66.609,32.342 66.79,32.342 66.88,32.252 66.88,32.201 66.97,32.111 67.151,32.111 67.241,32.201 67.241,32.238 67.331,32.328 67.512,32.328 67.602,32.238 67.602,32.205 67.696,32.111 68.3,32.111 68.311,32.111 69.05,32.85 69.05,33.026 69.05,33.106 68.955,33.2 68.869,33.2 68.797,33.273 68.797,33.489 68.869,33.561 68.955,33.561 69.05,33.656 69.05,34.116 v1(68.57,34.595)
SXM_PETX1_n: C45.1 P6.G13 TP5.1 | length 56
  Top Layer w0.161: C45.1@47.325,58 47.325,57.954 47.57,57.709 47.57,57.33 47.57,56.944 47.325,56.7 TP5.1@47.325,56.681 47.57,56.436 47.57,48.77 ccw(c50.418,48.77) 48.404,46.756 51.156,44.004 cw(c49.36,42.208) 51.9,42.208 51.9,32.66 53.176,31.385 53.371,31.189 60.611,31.189 v1(60.8,31) ; v1(69.84,38.405) P6.G13@70.475,37.77
  Bottom Layer w0.161: v1(60.8,31) 61.4,31 61.5,30.9 69.64,30.9 71.672,32.932 71.672,36.663 71.534,36.801 70.409,37.926 69.934,37.926 69.84,38.02 v1(69.84,38.405)
SXM_PETX1_p: C44.1 P6.G12 TP7.1 | length 55.9
  Top Layer w0.161: TP7.1@48.125,56.681 47.881,56.436 47.881,48.772 ccw(c50.421,48.772) 48.624,46.976 51.379,44.221 cw(c49.369,42.212) 52.211,42.212 52.211,32.789 53.2,31.8 53.5,31.5 v1(61.4,31.5) ; TP7.1@48.125,56.7 48.125,56.719 47.881,56.964 47.881,57.458 47.881,57.709 48.125,57.954 C44.1@48.125,58 ; P6.G12@69.205,37.77 v1(69.84,37.135)
  Bottom Layer w0.161: v1(61.4,31.5) 61.689,31.211 69.511,31.211 71.361,33.061 71.361,33.322 71.361,33.402 71.267,33.497 71.205,33.497 71.133,33.569 71.133,33.785 71.205,33.858 71.289,33.858 71.361,33.93 71.361,34.146 71.289,34.219 71.205,34.219 71.133,34.291 71.133,34.507 71.205,34.58 71.289,34.58 71.361,34.652 71.361,34.868 71.289,34.941 71.205,34.941 71.133,35.013 71.133,35.229 71.205,35.302 71.289,35.302 71.361,35.374 71.361,35.59 71.289,35.663 71.205,35.663 71.133,35.735 71.133,35.951 71.205,36.024 71.267,36.024 71.361,36.118 71.361,36.397 71.361,36.534 71.355,36.54 71.298,36.597 71.165,36.597 71.147,36.579 71.019,36.579 70.892,36.706 70.892,36.834 70.913,36.855 70.913,36.983 70.785,37.11 70.657,37.11 70.636,37.089 70.509,37.089 70.381,37.217 70.381,37.345 70.399,37.363 70.399,37.496 70.28,37.615 70.039,37.615 69.934,37.615 69.84,37.52 v1(69.84,37.135)
SXM_PETX2_n: C47.1 P6.H12 TP9.1 | length 52.7
  Top Layer w0.161: C47.1@45.7,60.2 ccw(c45.811,60.2) 45.733,60.121 cw(c45.221,59.61) 45.944,59.61 45.944,59.144 TP9.1@45.7,58.9 45.7,58.881 45.944,58.636 45.944,48.695 ccw(c48.793,48.695) 46.779,46.681 50.056,43.404 cw(c48.26,41.608) 50.8,41.608 50.8,32.36 53.071,30.089 62.915,30.089 65.105,32.28 65.105,32.636 65.3,32.831 v1(65.3,32.9) ; v1(68.57,35.865) P6.H12@69.205,36.5
  Bottom Layer w0.161: v1(65.3,32.9) 65.3,32.969 65.105,33.164 65.105,33.451 66.945,35.29 67.46,35.29 68.035,35.865 v1(68.57,35.865)
SXM_PETX2_p: C46.1 P6.H11 TP12.1 | length 52.7
  Top Layer w0.161: C46.1@46.5,60.2 cw(c46.389,60.2) 46.467,60.121 ccw(c46.979,59.61) 46.255,59.61 46.255,59.145 TP12.1@46.5,58.9 46.5,58.881 46.255,58.636 46.255,48.697 ccw(c48.795,48.697) 46.999,46.901 50.279,43.621 cw(c48.269,41.612) 51.111,41.612 51.111,32.489 53.2,30.4 62.786,30.4 64.794,32.409 64.794,32.636 64.6,32.831 v1(64.6,32.9) ; v1(67.3,35.865) P6.H11@67.935,36.5
  Bottom Layer w0.161: v1(64.6,32.9) 64.6,32.969 64.794,33.164 64.794,33.58 65.322,34.107 65.379,34.164 65.379,34.297 65.308,34.368 65.308,34.496 65.436,34.623 65.564,34.623 65.637,34.55 65.765,34.55 65.892,34.677 65.892,34.805 65.67,35.027 65.67,35.155 65.798,35.282 65.926,35.282 66.148,35.06 66.275,35.06 66.403,35.188 66.403,35.316 66.181,35.538 66.181,35.665 66.309,35.793 66.436,35.793 66.655,35.574 66.789,35.574 67.015,35.8 67.235,35.8 67.276,35.841 v1(67.3,35.865)
SXM_PETX3_n: C49.1 P6.K12 TP15.1 | length 51.8
  Top Layer w0.161: C49.1@44.1,58 44.1,57.954 44.344,57.71 44.344,57.364 44.1,57.119 TP15.1@44.1,57.1 44.1,57.081 44.345,56.836 44.345,48.395 ccw(c47.193,48.395) 45.179,46.381 48.956,42.604 cw(c47.16,40.808) 49.7,40.808 49.7,32.06 49.882,31.878 52.38,29.38 52.471,29.289 66.129,29.289 68.726,31.886 68.726,33.481 P6.K12@69.205,33.96
SXM_PETX3_p: C48.1 P6.K11 TP17.1 | length 51.8
  Top Layer w0.161: C48.1@44.9,58 44.9,57.954 44.655,57.71 44.655,57.364 44.9,57.119 TP17.1@44.9,57.1 44.9,57.081 44.656,56.836 44.656,48.397 ccw(c47.196,48.397) 45.399,46.601 49.179,42.821 cw(c47.169,40.812) 50.011,40.812 50.011,32.189 50.2,32 52.6,29.6 66,29.6 66.5,30.1 66.591,30.191 66.591,30.324 66.533,30.382 66.533,30.509 66.66,30.637 66.788,30.637 66.849,30.576 66.976,30.576 67.104,30.704 67.104,30.832 67.031,30.905 67.031,31.033 67.158,31.16 67.286,31.16 67.359,31.087 67.487,31.087 67.615,31.215 67.615,31.342 67.541,31.416 67.541,31.543 67.669,31.671 67.796,31.671 67.867,31.6 68,31.6 68.312,31.912 68.415,32.015 68.415,33.481 P6.K11@67.935,33.96
SXM_PWR_BREAK#: P6.E18 TP56.1 | length 24.4
  Top Layer w0.2: v1(76.19,40.945) P6.E18@76.825,40.31
  PWR w0.2: v1(76.19,40.945) 76.19,41.21 75.6,41.8 75.6,47.9 77.1,49.4 77.1,51.7 78.9,53.5 85.24,53.5 86.3,52.44 v1(86.3,51.9)
  Bottom Layer w0.2: TP56.1@86,51 v1(86.3,51.9)
SXM_PWR_EN: P6.A18 R32.2 R58.1 TP57.1 | length 89.1
  Top Layer w0.2: R58.1@38.5,96.6 v1(38.5,97.4) R32.2@38.5,98 ; v1(41.8,92.5) 41.8,92.1 51,82.9 51,55.1 52.9,53.2 76.8,53.2 79.5,50.5 ; P6.A18@76.825,45.39 77.5,46.065 77.5,47.3 79.5,49.3 79.5,50.5 ; v1(81.2,51.7) 80.7,51.2 80.2,51.2 79.5,50.5
  Bottom Layer w0.2: v1(38.5,97.4) 38.5,95.2 41.2,92.5 v1(41.8,92.5) ; v1(81.2,51.7) TP57.1@82,51
SXM_PWR_OVERT: P6.A19 TP59.1 | length 13.1
  Top Layer w0.2: P6.A19@78.095,45.39 78.095,47.295 79.9,49.1 79.9,50.3 80.4,50.8 81.6,50.8 82.7,51.9 82.7,52.5 83.1,52.9 83.7,52.9 84.3,52.3 v1(84.3,51.9)
  Bottom Layer w0.2: TP59.1@84,51 v1(84.3,51.9)
SXM_PWR_PWRGD: P6.K18 TP58.1 | length 6.7
  Top Layer w0.2: P6.K18@76.825,33.96 76.825,33.375 77.5,32.7 77.5,32 78.5,31 79.1,31 v1(79.6,30.5)
  Bottom Layer w0.2: v1(79.6,30.5) TP58.1@81,29.5
SYS_FAN_PWM: M1.6 R9.2 | length 98.1
  Top Layer w0.2: R9.2@25.5,20.7 25.5,21.9 26.6,23 33.6,23 41.2,30.6 41.2,73.8 39.2,75.8 39.2,83.81 39.485,84.095 v1(39.485,84.177) ; M1.6@36.1,100.125 37.533,100.125 37.892,100.484 v1(37.951,100.484)
  PWR w0.2: v1(37.951,100.484) 37.967,100.5 39.3,100.5 43.5,96.3 43.5,88.169 39.508,84.177 v1(39.485,84.177)
SYS_FAN_TAC: C9.2 M1.8 R8.2 R57.1 | length 98.6
  Top Layer w0.2: C9.2@24.6,20.7 R57.1@24.6,21.6 26.4,23.4 33.4,23.4 40.8,30.8 40.8,73.6 38.8,75.6 38.8,84.384 39.087,84.671 v1(39.087,84.752) ; M1.8@36.1,99.625 37.925,99.625 38.1,99.8 v1(38.143,99.8)
  Top Layer w0.3: R8.2@23.7,20.7 C9.2@24.6,20.7
  PWR w0.2: v1(38.143,99.8) 39.4,99.8 43.1,96.1 43.1,88.334 39.575,84.81 39.144,84.81 v1(39.087,84.752)
TMDS_CK_N: C33.1 D7.5 D7.6 P5.12 R55.2 | length 10.8
  Top Layer w0.161: P5.12@9.36,51.025 11.375,51.025 11.625,50.775 D7.6@12.582,50.775 ; D7.5@13.418,50.775 13.601,50.775 13.695,50.681 14.242,50.681 14.501,50.94 ; 14.501,50.941 15.416,51.855 16.009,51.855 16.554,52.4 R55.2@16.6,52.4 16.646,52.4 17.19,51.855 18.805,51.855 19.05,52.1 C33.1@19.096,52.1
  Top Layer w0.2: D7.6@12.692,50.775 D7.5@13.418,50.775
TMDS_CK_P: C32.1 D7.4 D7.7 P5.10 R53.2 | length 10.8
  Top Layer w0.161: P5.10@9.36,50.025 11.325,50.025 11.575,50.275 D7.7@12.582,50.275 ; D7.4@13.418,50.275 13.601,50.275 13.695,50.37 14.371,50.37 14.812,50.811 ; 14.812,50.812 15.544,51.544 16.009,51.544 16.554,51 R53.2@16.6,51 16.646,51 17.19,51.544 18.805,51.544 19.05,51.3 C32.1@19.096,51.3
  Top Layer w0.2: D7.7@12.692,50.275 D7.4@13.418,50.275
TMDS_D0_N: C31.1 D7.2 D7.9 P5.9 R51.2 | length 10.5
  Top Layer w0.161: P5.9@9.36,49.525 11.375,49.525 11.625,49.275 D7.9@12.582,49.275 ; D7.2@13.418,49.275 13.601,49.275 13.695,49.181 14.381,49.181 14.755,49.555 16.009,49.555 16.554,50.1 R51.2@16.6,50.1 16.646,50.1 17.19,49.555 18.805,49.555 19.05,49.8 C31.1@19.096,49.8
  Top Layer w0.2: D7.9@12.692,49.275 D7.2@13.418,49.275
TMDS_D0_P: C30.1 D7.1 D7.10 P5.7 R14.2 | length 10.5
  Top Layer w0.161: P5.7@9.36,48.525 11.325,48.525 11.335,48.535 11.396,48.535 11.635,48.775 D7.10@12.582,48.775 ; D7.1@13.418,48.775 13.601,48.775 13.695,48.87 14.509,48.87 14.884,49.244 16.009,49.244 16.554,48.7 R14.2@16.6,48.7 16.646,48.7 17.19,49.244 18.805,49.244 19.05,49 C30.1@19.096,49
  Top Layer w0.2: D7.10@12.692,48.775 D7.1@13.418,48.775
TMDS_D1_N: C29.1 D6.5 D6.6 P5.6 R56.1 | length 10.5
  Top Layer w0.161: P5.6@9.36,48.025 11.375,48.025 11.625,47.775 D6.6@12.582,47.775 ; D6.5@13.418,47.775 13.601,47.775 13.695,47.681 13.942,47.681 15.019,47.681 15.111,47.589 15.445,47.256 16.01,47.256 16.554,47.8 R56.1@16.6,47.8 16.646,47.8 17.19,47.256 18.805,47.256 19.05,47.5 C29.1@19.096,47.5
  Top Layer w0.2: D6.6@12.692,47.775 D6.5@13.418,47.775
TMDS_D1_P: C28.1 D6.4 D6.7 P5.4 R54.1 | length 10.5
  Top Layer w0.161: P5.4@9.36,47.025 11.325,47.025 11.575,47.275 D6.7@12.582,47.275 ; D6.4@13.418,47.275 13.601,47.275 13.695,47.37 14.071,47.37 14.891,47.37 15.316,46.945 16.01,46.945 16.554,46.4 R54.1@16.6,46.4 16.646,46.4 17.19,46.945 18.805,46.945 19.05,46.7 C28.1@19.096,46.7
  Top Layer w0.2: D6.7@12.692,47.275 D6.4@13.418,47.275
TMDS_D2_N: C27.1 D6.2 D6.9 P5.3 R52.1 | length 10.8
  Top Layer w0.161: P5.3@9.36,46.525 11.375,46.525 11.625,46.275 D6.9@12.582,46.275 ; D6.2@13.418,46.275 13.601,46.275 13.695,46.181 14.259,46.181 15.484,44.956 16.01,44.956 16.554,45.5 R52.1@16.6,45.5 16.646,45.5 17.19,44.956 18.805,44.956 19.05,45.2 C27.1@19.096,45.2
  Top Layer w0.2: D6.9@12.692,46.275 D6.2@13.418,46.275
TMDS_D2_P: C26.1 D6.1 D6.10 P5.1 R15.1 | length 10.8
  Top Layer w0.161: P5.1@9.36,45.525 11.325,45.525 11.575,45.775 D6.10@12.582,45.775 ; D6.1@13.418,45.775 13.601,45.775 13.695,45.87 14.13,45.87 14.4,45.6 15.355,44.645 16.01,44.645 16.554,44.1 R15.1@16.6,44.1 16.646,44.1 17.19,44.645 18.805,44.645 19.05,44.4 C26.1@19.096,44.4
  Top Layer w0.2: D6.10@12.692,45.775 D6.1@13.418,45.775
TMDS_HPD: D11.3 P5.19 R29.1 | length 4.8
  Top Layer w0.2: P5.19@9.36,54.525 11.125,54.525 R29.1@11.9,55.3 11.9,54.5 12.4,54 D11.3@12.85,54
TMDS_SCL: D11.5 P5.15 Q1.6 R27.1 | length 13.6
  Top Layer w0.2: P5.15@9.36,52.525 10.975,52.525 12.3,51.2 13.6,51.2 14.15,51.75 D11.5@14.15,52 14.15,52.25 14.4,52.5 15.2,52.5 16.9,54.2 R27.1@16.9,55.1 17.3,55.5 18.8,55.5 19.3,55 19.57,55 Q1.6@19.62,54.95
TMDS_SDA: D11.4 P5.16 Q1.3 R28.1 | length 11.3
  Top Layer w0.2: P5.16@9.36,53.025 11.075,53.025 12.1,52 D11.4@12.85,52 12.85,52.25 13.5,52.9 14.8,52.9 v1(16,54.1) R28.1@16,55.1 ; v1(16.9,53.3) 17.25,53.65 Q1.3@17.78,53.65
  Bottom Layer w0.2: v1(16,54.1) 16.1,54.1 v1(16.9,53.3)
TSENSE: M1.9 R17.2 | length 14.3
  Top Layer w0.2: M1.9@27.9,99.375 29.019,99.375 29.319,99.675 v1(29.4,99.675) ; v1(39.4,95.9) R17.2@39.4,96.5
  PWR w0.2: v1(29.4,99.675) 29.457,99.732 29.932,99.732 30.2,100 35,100 36.8,98.2 36.8,97.8 37.3,97.3 37.7,97.3 39.061,95.939 39.361,95.939 v1(39.4,95.9)
USB_1_n: D2.2 D2.9 M1.73 P4.2 | length 37.6
  Top Layer w0.161: v1(10.236,88.65) 10.255,88.65 10.5,88.405 13.105,88.405 13.199,88.5 D2.9@13.382,88.5 ; D2.2@14.218,88.5 14.4,88.5 14.495,88.405 16.434,88.405 17.32,87.52 17.32,86.08 19.634,83.766 25.534,83.766 26.02,83.28 27.011,83.28 27.036,83.305 27.831,83.305 M1.73@27.9,83.375
  Top Layer w0.2: D2.9@13.382,88.5 D2.2@14.218,88.5
  Bottom Layer w0.161: v1(10.236,88.65) 10.255,88.65 10.5,88.405 11.1,88.405 11.3,88.605 11.3,93.56 10.18,94.68 7.789,97.071 7.789,99.498 8.471,100.181 9.5,100.181 10.31,100.991 P4.2@10.31,101 P4.2@10.31,101.025
USB_1_p: D2.1 D2.10 M1.75 P4.3 | length 37.6
  Top Layer w0.161: v1@10.255,87.85 10.5,88.094 13.105,88.094 13.199,88 D2.10@13.382,88 ; D2.1@14.218,88 14.4,88 14.495,88.094 16.306,88.094 16.9,87.5 17.009,87.391 17.009,85.951 19.505,83.455 25.405,83.455 25.891,82.969 27.011,82.969 27.036,82.944 27.831,82.944 M1.75@27.9,82.875
  Top Layer w0.2: D2.10@13.382,88 D2.1@14.218,88
  Bottom Layer w0.161: v1(10.236,87.85) 10.255,87.85 10.5,88.094 11.229,88.094 11.611,88.477 11.611,93.689 8.1,97.2 8.1,99.37 8.6,99.87 9.5,99.87 10.31,99.06 P4.3@10.31,99.025
USB_1_VBUS: C13.1 F5.2 P4.1
USB_2_n: D2.5 D2.6 M1.67 P4.11 | length 37
  Top Layer w0.161: D2.6@13.382,90 13.199,90 13.105,89.905 11.995,89.905 11.2,90.7 11.2,94.04 9.1,96.14 9.1,97 9.6,97.5 10.6,97.5 11.1,97 11.269,96.83 12.387,96.83 13.404,97.848 13.814,98.056 13.893,98.097 13.916,98.12 14.364,98.657 14.364,99.364 13.9,100 13.547,100.963 P4.11@13.51,101 ; D2.5@14.218,90 14.4,90 14.495,89.905 17.334,89.905 17.425,89.814 18.5,88.74 18.5,86.5 18.8,86.2 20.489,84.511 25.471,84.511 25.741,84.78 27.011,84.78 27.036,84.805 27.831,84.805 M1.67@27.9,84.875
  Top Layer w0.2: D2.6@13.382,90 D2.5@14.218,90
USB_2_p: D2.4 D2.7 M1.69 P4.12 | length 37
  Top Layer w0.161: D2.7@13.382,89.5 13.199,89.5 13.105,89.594 11.866,89.594 10.889,90.571 10.889,93.911 9.4,95.4 8.789,96.011 8.789,97.129 9.471,97.811 10.729,97.811 11.398,97.141 12.259,97.141 12.9,97.783 12.9,98.2 12.4,98.7 12.4,99.2 12.9,99.7 13.2,99.7 13.51,99.39 P4.12@13.51,99 ; D2.4@14.218,89.5 14.4,89.5 14.495,89.594 17.206,89.594 18.189,88.611 18.189,86.371 18.385,86.176 20.36,84.2 25.6,84.2 25.869,84.469 27.011,84.469 27.036,84.444 27.831,84.444 M1.69@27.9,84.375
  Top Layer w0.2: D2.7@13.382,89.5 D2.4@14.218,89.5
USB_2_VBUS: C16.1 F6.2 P4.10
